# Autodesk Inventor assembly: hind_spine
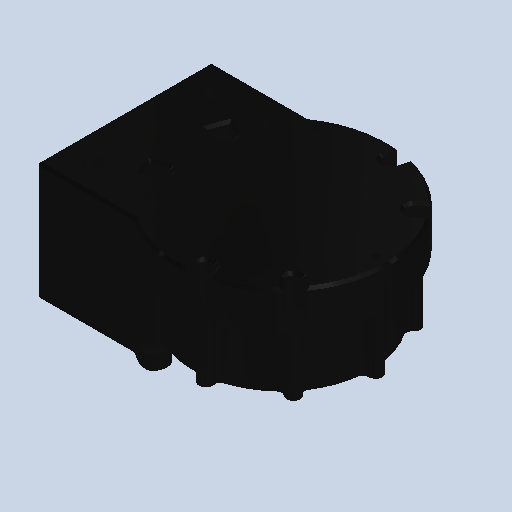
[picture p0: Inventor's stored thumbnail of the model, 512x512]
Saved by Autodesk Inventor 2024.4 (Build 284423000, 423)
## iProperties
Created: 2026-01
Part Number: hind_spine
Document SubType Name: Assembly
Designer: AdminForWorker
Title: hind_spine v1
Author: AdminForWorker
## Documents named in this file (4)
- c:\worker\convert-fusion-r06-cosv3\tmp\job-1\1\temp\files\005d4993-bbfc-4a7a-8441-a28d296e97d0\ad9b68a5-8340-4366-93e5-3e3480a2d771.iam
- c:\worker\convert-fusion-r06-cosv3\tmp\job-1\1\temp\files\005d4993-bbfc-4a7a-8441-a28d296e97d0\CyberGear.ipt
- c:\worker\convert-fusion-r06-cosv3\tmp\job-1\1\temp\files\005d4993-bbfc-4a7a-8441-a28d296e97d0\body_split1.ipt
- c:\worker\convert-fusion-r06-cosv3\tmp\job-1\1\temp\files\005d4993-bbfc-4a7a-8441-a28d296e97d0\front_body.ipt
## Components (3 placed, 3 different names)
1. CyberGear:1
2. body_split1:1
3. front_body:1
